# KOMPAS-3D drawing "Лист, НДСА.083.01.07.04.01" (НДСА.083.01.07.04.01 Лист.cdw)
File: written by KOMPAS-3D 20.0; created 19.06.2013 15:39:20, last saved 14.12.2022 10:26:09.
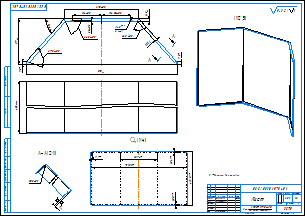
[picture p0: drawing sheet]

Sheet 1: A2, landscape

Document properties: Автор: Шубников; Знак неуказанной шероховатости: 4; Параметр неуказанной шероховатости: Ra3.2; Полное имя файла: НДСА.083.01.07.04.01 Лист.m3d; PLM_CDWXDTO: <item xmlns="http://appius.ru/pdm" xmlns:xs="http://www.w3.org/2001/XMLSchema" xmlns:xsi="http://www.w3.org/2001/XMLSchema-instance" xsi:type="item">  <element xmlns:d2p1="http://v8.1c.ru/8.1/data/enterprise/current-config" xsi:type="d2p1:CatalogRef.aps_Элемен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; Масса: 2.51004; PDM_DOCXDTO: <item xmlns="http://appius.ru/pdm" xmlns:xs="http://www.w3.org/2001/XMLSchema" xmlns:xsi="http://www.w3.org/2001/XMLSchema-instance" xsi:type="item">  <element xmlns:d2p1="http://v8.1c.ru/8.1/data/enterprise/current-config" xsi:type="d2p1:CatalogRef.aps_Элемен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; PDM_ITEMXDTO: <item xmlns="http://appius.ru/pdm" xmlns:xs="http://www.w3.org/2001/XMLSchema" xmlns:xsi="http://www.w3.org/2001/XMLSchema-instance" xsi:type="item">  <element xmlns:d2p1="http://v8.1c.ru/8.1/data/enterprise/current-config" xsi:type="d2p1:CatalogRef.aps_Элемен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; PDM_DRAWINGXDTO: <item xmlns="http://appius.ru/pdm" xmlns:xs="http://www.w3.org/2001/XMLSchema" xmlns:xsi="http://www.w3.org/2001/XMLSchema-instance" xsi:type="item">  <element xmlns:d2p1="http://v8.1c.ru/8.1/data/enterprise/current-config" xsi:type="d2p1:CatalogRef.aps_Элемен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; Организация: ЭСТО-Вакуум

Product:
- Part/product: Лист  | designation НДСА.083.01.07.04.01
    Материал: Лист$d1 ГОСТ 19904-90;10 ГОСТ 16523-97$ (density 7856 kg/m3)
    Масса: 2.51004
    additional columns: <item xmlns="http://appius.ru/pdm" xmlns:xs="http://www.w3.org/2001/XMLSchema" x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; <item xmlns="http://appius.ru/pdm" xmlns:xs="http://www.w3.org/2001/XMLSchema" x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; <item xmlns="http://appius.ru/pdm" xmlns:xs="http://www.w3.org/2001/XMLSchema" x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
    source file: НДСА.083.01.07.04.01 Лист.cdw

Title block, sheet 1: Наименование: Лист; designation: НДСА.083.01.07.04.01; Материал: Лист 1 ГОСТ 19904-90 10 ГОСТ 16523-97; Масса: 2,51; scale: 1:2; Количество листов документа: 1; organisation: ЭСТО; Форматы листов документа: A2; stored path: C:\Пищагина\Чертежи Ялика\УКРД.839.01.06.04.01 - Лист.cdw; Разработал: Щербакова; Проверил: Горностаев; Утвердил: Белецкий; Разработал, date: 13.12.2022

Views: Снизу 1, Снизу, Проекционный вид 2, Разрез А-А, Вид 5, Развертка
Referenced files in C:\Users\cherbakova\Desktop\Виноград\Новая папка (4)\: НДСА.083.01.07.04.01 Лист.m3d
Referenced files in C:\Users\reznika\Desktop\Конвертация\Крышка камеры\Новая крышка\: НДСА.015.01.06.03.01 Лист.m3d
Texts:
  Ra3.2
  Ra3.2 ( )
  НДСА.083.01.07.04.01 Лист
Dimensions and other numbers on the sheet: 114±0,5; 114,05±0,5; 11,5; 177; 9,5; 590; 290±0,5; 5,5±0,3; 4,5; 2 отв.; 48,1; 66,5; 67,5; 403; 1; 0,5; 5; 289,4; 9,7; 731,88; 10,67; 422,67; 1:2; 2,51; 13.12.2022

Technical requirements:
  *Размеры для справок.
